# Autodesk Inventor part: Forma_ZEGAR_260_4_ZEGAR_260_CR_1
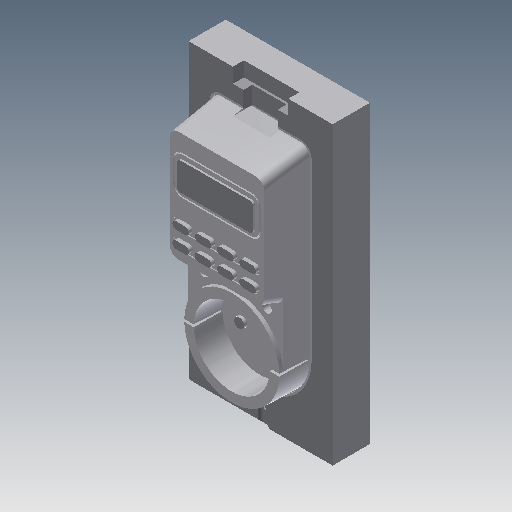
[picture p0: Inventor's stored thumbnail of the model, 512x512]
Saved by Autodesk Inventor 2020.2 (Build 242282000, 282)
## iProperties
Created: 2015-01
Part Number: Forma_ZEGAR_260_4_ZEGAR_260_CR_1
Material: Ogólny
Document SubType Name: Modeling
Designer: F.Stasiak
Density: 1 g/cm^3
Appearance: Domyślna
Catalog Web Link: www.expertbooks.pl
Manager: www.cadconsulting.pl
Company: Fabian Stasiak CAD Consulting
Author: F.Stasiak
Subject: Zbiór ćwiczeń. Autodesk Inventor 2020. Kurs Professional
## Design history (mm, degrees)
node "Forma_ZEGAR_260_4_ZEGAR_260_CR_Base"
feature "Rzeźbienie3"
feature "Bryła1::Forma_ZEGAR_260_4_ZEGAR_260_CR_Base"
tag "Bryła wyprowadzona1"
node "Bryła1"
feature "Forma_ZEGAR_260_4_ZEGAR_260_CR_Base_Bodies"
feature "Powierzchnia3"
body "Srf3"
